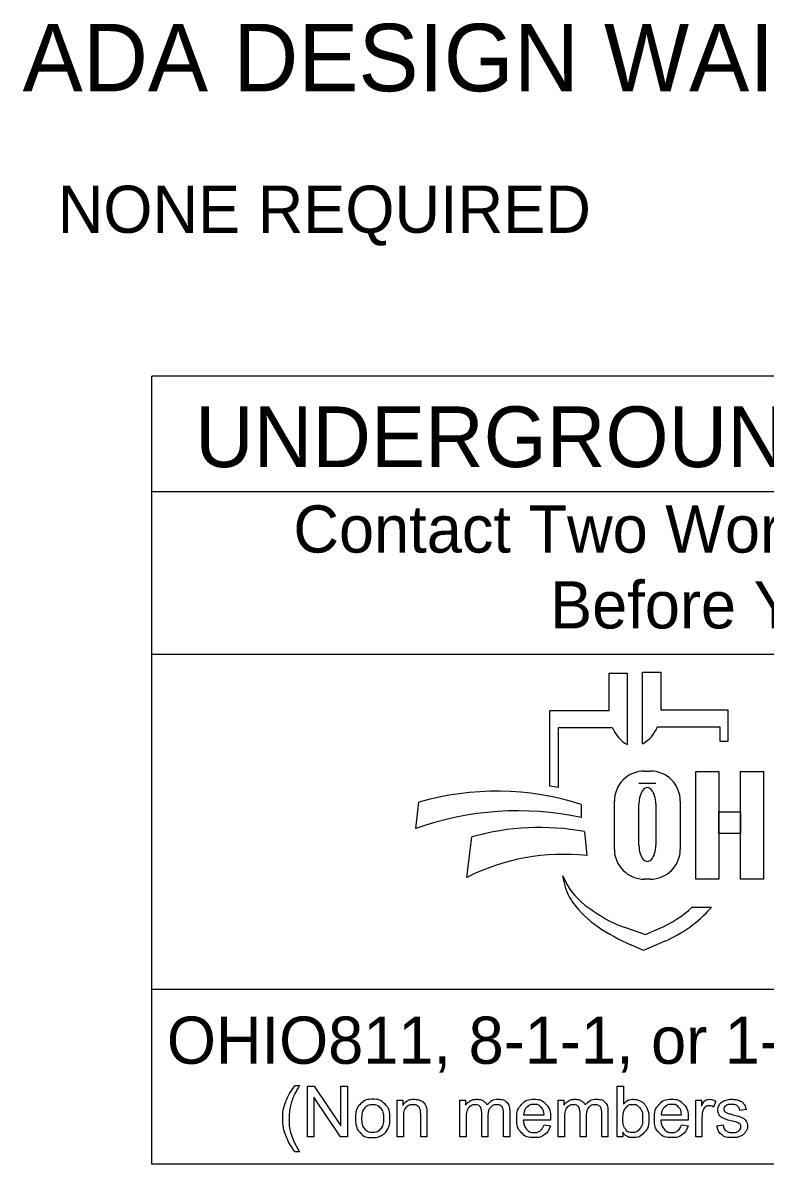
# Model space of a CAD drawing. Extents: x 0 to 91.3, y -0.7 to 22.
# Drawn here: x 1.995 to 4.196, y 2.143 to 5.529 of the extents above; entities that cross this region are included whole.
import ezdxf

# ---------------------------------------------------------------- set-up
doc = ezdxf.new("R2010")
doc.units = 0
doc.layers.add('SH_Data', color=7, linetype='Continuous')
doc.layers.add('SH_Text', color=7, linetype='Continuous')

msp = doc.modelspace()

# ---------------------------------------------------------------- linework, layer by layer
at = {"layer": 'SH_Data'}
for p, q in [((2.3775, 2.1428), (2.3775, 4.4803)), ((6.6275, 4.4803), (2.3775, 4.4803)), ((2.3775, 4.1387), (6.6275, 4.1387)), ((2.3775, 3.6553), (6.6275, 3.6553)), ((6.6275, 2.6607), (2.3775, 2.6607)), ((6.6275, 2.1428), (2.3775, 2.1428))]:
    msp.add_line(p, q, dxfattribs=at)
at = {"layer": 'SH_Text'}
for p, q in [((3.7335, 3.4883), (3.7335, 3.5998)), ((3.7335, 3.5998), (3.7872, 3.5998)), ((3.7872, 3.5998), (3.7872, 3.3877)), ((3.8329, 3.39), (3.8329, 3.6021)), ((3.8329, 3.6021), (3.8865, 3.6021)), ((3.8865, 3.6021), (3.8865, 3.4906)), ((3.5576, 3.2644), (3.5576, 3.4883)), ((3.5576, 3.4883), (3.7335, 3.4883)), ((3.8865, 3.4906), (4.0857, 3.4906)), ((4.0857, 3.4906), (4.0857, 3.3968)), ((3.5828, 3.4369), (3.5828, 3.26)), ((3.7439, 3.4369), (3.5828, 3.4369)), ((4.0625, 3.4392), (3.8761, 3.4392)), ((4.0625, 3.3968), (4.0625, 3.4392)), ((4.0857, 3.3968), (4.0625, 3.3968)), ((3.8385, 3.3091), (3.8551, 3.3091)), ((3.8718, 3.2721), (3.822, 3.2721)), ((3.7491, 3.0776), (3.7491, 3.2196)), ((3.9445, 3.2196), (3.9445, 3.0776)), ((3.1602, 3.1381), (3.1696, 3.2162)), ((3.6509, 3.2097), (3.6509, 3.1709)), ((3.822, 3.089), (3.822, 3.2114)), ((3.8718, 3.2114), (3.8718, 3.089)), ((3.6608, 3.1291), (3.6671, 3.0582)), ((3.312, 2.9936), (3.3267, 3.1137)), ((3.5997, 2.9807), (3.5967, 2.9986)), ((3.8551, 2.9882), (3.8385, 2.9882)), ((3.98, 2.9048), (4.0375, 2.9048)), ((3.7816, 2.8444), (3.841, 2.8239)), ((3.841, 2.8239), (3.8821, 2.8417)), ((3.835, 2.7769), (3.7976, 2.7934)), ((3.8983, 2.8044), (3.835, 2.7769))]:
    msp.add_line(p, q, dxfattribs=at)
for points in [[(3.991, 3.3081), (4.0589, 3.3081), (4.0589, 2.9881), (3.991, 2.9881)], [(4.1231, 3.3081), (4.1911, 3.3081), (4.1911, 2.9881), (4.1231, 2.9881)], [(4.0589, 3.1882), (4.1231, 3.1882), (4.1231, 3.1242), (4.0589, 3.1242)]]:
    msp.add_lwpolyline(points, close=True, dxfattribs=at)
for points in [[(2.8021, 2.3766), (2.8153, 2.3766)], [(2.8389, 2.2239), (2.8389, 2.3741), (2.8592, 2.3741), (2.9382, 2.2561), (2.9382, 2.3741), (2.9572, 2.3741), (2.9572, 2.2239), (2.9369, 2.2239), (2.8579, 2.3419), (2.8579, 2.2239), (2.8389, 2.2239)], [(3.7743, 2.2239), (3.7573, 2.2239), (3.7573, 2.3741), (3.7757, 2.3741), (3.7757, 2.3206)], [(3.1048, 2.2239), (3.1048, 2.3328), (3.1214, 2.3328), (3.1214, 2.3173)], [(3.2912, 2.2239), (3.2912, 2.3328), (3.3077, 2.3328), (3.3077, 2.3174)], [(3.5826, 2.2239), (3.5826, 2.3328), (3.5991, 2.3328), (3.5991, 2.3174)], [(3.9904, 2.2239), (3.9904, 2.3328), (4.007, 2.3328), (4.007, 2.3163)], [(4.0495, 2.3293), (4.043, 2.3122)], [(4.1394, 2.3046), (4.1213, 2.3022)], [(3.1233, 2.2833), (3.1233, 2.2239), (3.1048, 2.2239)], [(3.1932, 2.2908), (3.1932, 2.2239), (3.1748, 2.2239), (3.1748, 2.2901)], [(3.3097, 2.2803), (3.3097, 2.2239), (3.2912, 2.2239)], [(3.3743, 2.2871), (3.3743, 2.2239), (3.3559, 2.2239), (3.3559, 2.2946)], [(3.4388, 2.2986), (3.4388, 2.2239), (3.4203, 2.2239), (3.4203, 2.2924)], [(3.56, 2.2736), (3.4788, 2.2736)], [(3.4799, 2.2887), (3.5406, 2.2887)], [(3.601, 2.2803), (3.601, 2.2239), (3.5826, 2.2239)], [(3.6657, 2.2871), (3.6657, 2.2239), (3.6473, 2.2239), (3.6473, 2.2946)], [(3.7301, 2.2986), (3.7301, 2.2239), (3.7117, 2.2239), (3.7117, 2.2924)], [(3.968, 2.2736), (3.8868, 2.2736)], [(3.8879, 2.2887), (3.9486, 2.2887)], [(4.0088, 2.2809), (4.0088, 2.2239), (3.9904, 2.2239)], [(3.5404, 2.2591), (3.5595, 2.2567)], [(3.7743, 2.2375), (3.7743, 2.2239)], [(3.9484, 2.2591), (3.9675, 2.2567)], [(4.053, 2.2564), (4.0712, 2.2593)], [(2.8153, 2.1798), (2.8021, 2.1798)]]:
    msp.add_lwpolyline(points, dxfattribs=at)
for centre, radius, start, end in [((3.8353, 3.4736), 0.0985, 201.9296, 240.7469), ((3.7847, 3.476), 0.0985, 299.2531, 338.0704), ((3.8385, 3.2196), 0.0895, 90, 180), ((3.8551, 3.2196), 0.0895, 0, 90), ((3.4295, 2.4554), 0.8191, 79.2074, 81.0007), ((3.3997, 2.4302), 0.8191, 72.1402, 106.3144), ((3.4628, 2.2991), 0.8919, 77.8238, 109.8274), ((3.5267, 2.4094), 0.7322, 79.44, 105.8467), ((3.5987, 2.4262), 0.6357, 83.8248, 116.8021), ((3.8385, 3.0776), 0.0895, 180, 270), ((3.8551, 3.0776), 0.0895, 270, 0), ((3.7841, 3.0707), 0.2008, 201.0457, 232.5314), ((3.741, 3.0048), 0.1433, 189.6817, 216.0884), ((3.8747, 3.1022), 0.3088, 216.0884, 235.7167), ((3.9766, 3.3219), 0.5173, 232.5314, 241.794), ((3.7387, 3.1722), 0.3602, 293.4582, 312.0712), ((3.7387, 3.1722), 0.401, 293.4582, 317.8286), ((4.0412, 3.3465), 0.6044, 235.7167, 246.2325), ((3.8914, 3.1631), 0.3371, 241.794, 250.9821)]:
    msp.add_arc(centre, radius, start, end, dxfattribs=at)
for centre, start_param, end_param in [((3.8469, 3.2114), 4.712389, 7.853982), ((3.8469, 3.089), 1.570796, 4.712389)]:
    msp.add_ellipse(centre, major_axis=(0, 0.0484), ratio=0.514403, start_param=start_param, end_param=end_param, dxfattribs=at)
for points in [[(2.8021, 2.1798), (2.7869, 2.199), (2.7763, 2.2248), (2.7657, 2.2506), (2.7657, 2.2783), (2.7657, 2.3026), (2.7736, 2.325), (2.7829, 2.3509), (2.8021, 2.3766)], [(2.8153, 2.3766), (2.8029, 2.3553), (2.7989, 2.3462), (2.7927, 2.332), (2.7891, 2.3167), (2.7847, 2.2975), (2.7847, 2.2782), (2.7847, 2.2289), (2.8153, 2.1798)], [(2.9814, 2.2783), (2.9814, 2.3085), (2.9981, 2.3231), (3.0122, 2.3352), (3.0323, 2.3352), (3.0547, 2.3352), (3.069, 2.3205), (3.0832, 2.3058), (3.0832, 2.2799), (3.0832, 2.2589), (3.0769, 2.2469), (3.0706, 2.2348), (3.0586, 2.2282), (3.0466, 2.2215), (3.0323, 2.2215), (3.0095, 2.2215), (2.9954, 2.2362), (2.9814, 2.2508), (2.9814, 2.2783)], [(3.0003, 2.2783), (3.0003, 2.2574), (3.0094, 2.247), (3.0185, 2.2366), (3.0323, 2.2366), (3.046, 2.2366), (3.0551, 2.2471), (3.0642, 2.2575), (3.0642, 2.279), (3.0642, 2.2991), (3.0551, 2.3095), (3.0459, 2.3199), (3.0323, 2.3199), (3.0185, 2.3199), (3.0094, 2.3096), (3.0003, 2.2992), (3.0003, 2.2783)], [(3.1214, 2.3173), (3.1334, 2.3352), (3.156, 2.3352), (3.1659, 2.3352), (3.1741, 2.3316), (3.1823, 2.3281), (3.1864, 2.3224), (3.1905, 2.3166), (3.1922, 2.3087), (3.1932, 2.3036), (3.1932, 2.2908)], [(3.1748, 2.2901), (3.1748, 2.3013), (3.1726, 2.3069), (3.1705, 2.3125), (3.165, 2.3158), (3.1595, 2.3191), (3.1521, 2.3191), (3.1404, 2.3191), (3.1318, 2.3117), (3.1233, 2.3042), (3.1233, 2.2833)], [(3.3077, 2.3174), (3.3128, 2.3254), (3.3214, 2.3303), (3.3299, 2.3352), (3.3407, 2.3352), (3.3528, 2.3352), (3.3606, 2.3301), (3.3683, 2.3251), (3.3715, 2.3161), (3.3844, 2.3352), (3.4051, 2.3352), (3.4213, 2.3352), (3.43, 2.3262), (3.4388, 2.3172), (3.4388, 2.2986)], [(3.3559, 2.2946), (3.3559, 2.3069), (3.3514, 2.313), (3.3469, 2.3191), (3.3366, 2.3191), (3.3288, 2.3191), (3.3222, 2.315), (3.3156, 2.311), (3.3126, 2.3031), (3.3097, 2.2952), (3.3097, 2.2803)], [(3.4203, 2.2924), (3.4203, 2.3035), (3.4185, 2.3083), (3.4168, 2.3132), (3.412, 2.3162), (3.4073, 2.3191), (3.401, 2.3191), (3.3895, 2.3191), (3.3819, 2.3115), (3.3743, 2.3039), (3.3743, 2.2871)], [(3.5595, 2.2567), (3.555, 2.24), (3.5428, 2.2307), (3.5306, 2.2215), (3.5117, 2.2215), (3.4878, 2.2215), (3.4738, 2.2362), (3.4598, 2.2509), (3.4598, 2.2774), (3.4598, 2.3049), (3.474, 2.32), (3.4881, 2.3352), (3.5106, 2.3352), (3.5324, 2.3352), (3.5463, 2.3203), (3.5601, 2.3055), (3.5601, 2.2785), (3.5601, 2.2769), (3.56, 2.2736)], [(3.5406, 2.2887), (3.5394, 2.3025), (3.5337, 2.3094), (3.5249, 2.3201), (3.5108, 2.3201), (3.4981, 2.3201), (3.4894, 2.3115), (3.4808, 2.303), (3.4799, 2.2887)], [(3.5991, 2.3174), (3.6042, 2.3254), (3.6127, 2.3303), (3.6212, 2.3352), (3.6321, 2.3352), (3.6442, 2.3352), (3.6519, 2.3301), (3.6597, 2.3251), (3.6628, 2.3161), (3.6758, 2.3352), (3.6965, 2.3352), (3.7127, 2.3352), (3.7214, 2.3262), (3.7301, 2.3172), (3.7301, 2.2986)], [(3.6473, 2.2946), (3.6473, 2.3069), (3.6428, 2.313), (3.6383, 2.3191), (3.628, 2.3191), (3.6202, 2.3191), (3.6136, 2.315), (3.607, 2.311), (3.604, 2.3031), (3.601, 2.2952), (3.601, 2.2803)], [(3.7117, 2.2924), (3.7117, 2.3035), (3.7099, 2.3083), (3.7081, 2.3132), (3.7034, 2.3162), (3.6987, 2.3191), (3.6923, 2.3191), (3.6809, 2.3191), (3.6733, 2.3115), (3.6657, 2.3039), (3.6657, 2.2871)], [(3.7741, 2.2792), (3.7741, 2.2596), (3.7794, 2.2509), (3.7881, 2.2366), (3.8029, 2.2366), (3.815, 2.2366), (3.8238, 2.2471), (3.8326, 2.2576), (3.8326, 2.2784), (3.8326, 2.2998), (3.8241, 2.3099), (3.8157, 2.3201), (3.8038, 2.3201), (3.7917, 2.3201), (3.7829, 2.3096), (3.7741, 2.299), (3.7741, 2.2792)], [(3.7757, 2.3206), (3.7874, 2.3352), (3.8055, 2.3352), (3.8155, 2.3352), (3.8245, 2.3311), (3.8335, 2.3271), (3.8392, 2.3198), (3.845, 2.3124), (3.8483, 2.3021), (3.8516, 2.2918), (3.8516, 2.28), (3.8516, 2.252), (3.8378, 2.2368), (3.8239, 2.2215), (3.8046, 2.2215), (3.7853, 2.2215), (3.7743, 2.2375)], [(3.9675, 2.2567), (3.963, 2.24), (3.9508, 2.2307), (3.9386, 2.2215), (3.9196, 2.2215), (3.8958, 2.2215), (3.8818, 2.2362), (3.8678, 2.2509), (3.8678, 2.2774), (3.8678, 2.3049), (3.882, 2.32), (3.8961, 2.3352), (3.9186, 2.3352), (3.9404, 2.3352), (3.9543, 2.3203), (3.9681, 2.3055), (3.9681, 2.2785), (3.9681, 2.2769), (3.968, 2.2736)], [(3.9486, 2.2887), (3.9474, 2.3025), (3.9417, 2.3094), (3.9328, 2.3201), (3.9188, 2.3201), (3.9061, 2.3201), (3.8974, 2.3115), (3.8888, 2.303), (3.8879, 2.2887)], [(4.007, 2.3163), (4.0133, 2.3278), (4.0187, 2.3315), (4.0241, 2.3352), (4.0305, 2.3352), (4.0398, 2.3352), (4.0495, 2.3293)], [(4.043, 2.3122), (4.0363, 2.3162), (4.0295, 2.3162), (4.0235, 2.3162), (4.0187, 2.3125), (4.0139, 2.3089), (4.0119, 2.3024), (4.0088, 2.2926), (4.0088, 2.2809)], [(4.1213, 2.3022), (4.1201, 2.3106), (4.1142, 2.3153), (4.1083, 2.3201), (4.0975, 2.3201), (4.0848, 2.3201), (4.0794, 2.3159), (4.0739, 2.3116), (4.0739, 2.306), (4.0739, 2.3024), (4.0762, 2.2995), (4.0785, 2.2966), (4.0833, 2.2946), (4.086, 2.2936), (4.0996, 2.2899), (4.1192, 2.2847), (4.1269, 2.2813), (4.1347, 2.278), (4.1391, 2.2717), (4.1435, 2.2653), (4.1435, 2.2559), (4.1435, 2.2467), (4.1381, 2.2386), (4.1327, 2.2304), (4.1226, 2.226), (4.1124, 2.2215), (4.0996, 2.2215), (4.0784, 2.2215), (4.0672, 2.2303), (4.0561, 2.2391), (4.053, 2.2564)], [(4.0712, 2.2593), (4.0727, 2.2483), (4.0798, 2.2425), (4.0868, 2.2366), (4.0995, 2.2366), (4.1122, 2.2366), (4.1184, 2.2418), (4.1245, 2.247), (4.1245, 2.254), (4.1245, 2.2602), (4.1191, 2.2638), (4.1153, 2.2663), (4.1002, 2.2701), (4.0799, 2.2752), (4.072, 2.2789), (4.0642, 2.2827), (4.0601, 2.2893), (4.0561, 2.2959), (4.0561, 2.3038), (4.0561, 2.3111), (4.0594, 2.3173), (4.0628, 2.3235), (4.0685, 2.3276), (4.0728, 2.3308), (4.0803, 2.333), (4.0877, 2.3352), (4.0962, 2.3352), (4.109, 2.3352), (4.1187, 2.3315), (4.1284, 2.3278), (4.133, 2.3215), (4.1377, 2.3152), (4.1394, 2.3046)], [(3.4788, 2.2736), (3.4799, 2.2557), (3.489, 2.2462), (3.4981, 2.2366), (3.5117, 2.2366), (3.5219, 2.2366), (3.5291, 2.242), (3.5362, 2.2473), (3.5404, 2.2591)], [(3.8868, 2.2736), (3.8879, 2.2557), (3.897, 2.2462), (3.9061, 2.2366), (3.9197, 2.2366), (3.9299, 2.2366), (3.937, 2.242), (3.9442, 2.2473), (3.9484, 2.2591)]]:
    msp.add_open_spline(points, degree=3, dxfattribs=at)

# ---------------------------------------------------------------- texts
for s, height, p in [('ADA DESIGN WAIVERS', 0.2, (1.9944, 5.3256)), ('  NONE REQUIRED', 0.14, (1.9944, 4.9056)), ('UNDERGROUND UTILITIES', 0.18, (2.5057, 4.2106)), ('Contact Two Working Days', 0.14, (2.7972, 3.9571)), ('Before You Dig', 0.14, (3.5583, 3.7321)), ('OHIO811, 8-1-1, or 1-800-362-2764', 0.14, (2.422, 2.4406))]:
    msp.add_text(s, height=height, dxfattribs=at).set_placement(p)

doc.saveas('drawing.dxf')
